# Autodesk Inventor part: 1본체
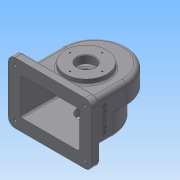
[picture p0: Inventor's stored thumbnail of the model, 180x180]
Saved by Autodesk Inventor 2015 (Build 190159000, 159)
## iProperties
Created: 2017-11
Part Number: 1본체
Material: 일반
Document SubType Name: Modeling
Designer: user
Density: 1 g/cm^3
Appearance: 기본값
Author: user
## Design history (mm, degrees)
sketch "스케치1"
  geometry: L1 (-58, -80)-(58, -80); L2 (-58, 0)-(-58, -80); L3 (58, 0)-(58, -80); A1 r 58 centre (0, 0) between (58, 0) and (-58, 0); 1 further point
  constraints: 6 end point, 2 point on circle, 2 tangent, 2 vertical, 1 centre point, 1 coincident, 1 horizontal
  dimensions: "d0" = 116 diameter of A1; "d1" = 80 distance from line of L1 point (0, 0)
extrude "돌출1" new body sketch "스케치1" stored distance "d2" = 38; taper "d3" = 0 deg
sketch "스케치2"
  geometry: L1 (-58, -80)-(58, -80) reference; L2 (58, -80)-(58, 0) reference; L3 (-58, 0)-(-58, -80) reference; L4 (-58, -80)-(58, -80); L5 (-58, -80)-(-58, -23); L6 (58, -80)-(58, -23); A1 r 58 centre (0, 0) between (58, 0) and (-58, 0) reference; A2 r 58 centre (0, -23) between (58, -23) and (-58, -23)
  constraints: 6 end point, 2 point on circle, 2 point on line, 1 centre point, 1 horizontal
  dimensions: "d6" = 57 distance from line of L1 A2.centre; "d7" = 58 radius of A2; "d8" = 23 distance of A1.centre A2.centre
extrude "돌출2" join sketch "스케치2" distance "d9" = 38; taper "d10" = 0 deg
sketch "스케치3"
  geometry: L1 (-58, -80)-(58, -80) reference; C1 r 37.5 at (0, -15); A1 r 58 centre (0, 0) between (58, 0) and (-58, 0) reference
  constraints: 1 centre point, 1 vertical alignment
  dimensions: "d11" = 75 diameter of C1; "d12" = 65 distance from line of L1 C1.centre
sketch "스케치4"
  geometry: L1 (-58, -80)-(58, -80) reference; C1 r 31 at (0, -15); 1 further point
  constraints: 1 centre point, 1 vertical alignment
  dimensions: "d13" = 62 diameter of C1; "d14" = 65 distance from line of L1 C1.centre
node "작업 평면1"
feature "쉘2" dims "d24" = 5
fillet "모깎기1" dims "d25" = 3
fillet "모깎기2" dims "d26" = 8
fillet "모깎기3" dims "d27" = 3
node "작업 평면2"
sketch "스케치6"
  geometry: L1 (-50, 19)-(50, 19) reference; C1 r 6 at (0, 0); 1 further point
  constraints: 1 centre point, 1 coincident
  dimensions: "d29" = 12 diameter of C1; "d30" = 19 distance from line of L1 C1.centre
extrude "돌출6" join sketch "스케치6" distance "d31" = 10; taper "d32" = 0 deg
extrude "돌출7" join sketch "스케치3" distance "d33" = 9; taper "d34" = 0 deg
extrude "돌출8" join sketch "스케치4" distance "d35" = 10; taper "d36" = 0 deg
sketch "스케치7"
  geometry: C1 r 37.5 at (0, 0) reference; C2 r 16 at (0, 0); 1 further point
  constraints: 1 centre point, 1 coincident
  dimensions: "d37" = 32 diameter of C2
extrude "돌출9" cut sketch "스케치7" distance "d38" = 21.75; taper "d39" = 0 deg
sketch "스케치8"
  geometry: C1 r 31 at (0, 0) reference; C2 r 16 at (0, 0); 1 further point
  constraints: 1 centre point, 1 coincident
  dimensions: "d40" = 32 diameter of C2
extrude "돌출10" cut sketch "스케치8" distance "d41" = 36.25; taper "d42" = 0 deg
sketch "스케치9"
  geometry: L1 (0, 0)-(100, 0) reference; L2 (-8, -8)-(-8, -68) reference; L3 (100, -76)-(0, -76) reference; L4 (108, -68)-(108, -8) reference; L5 (113, 17)-(-13, 17); L6 (-25, 5)-(-25, -81); L7 (-13, -93)-(113, -93); L8 (125, -81)-(125, 5); A1 r 8 centre (100, -8) between (108, -8) and (100, 0) reference; A2 r 8 centre (0, -8) between (0, 0) and (-8, -8) reference; A3 r 8 centre (0, -68) between (-8, -68) and (0, -76) reference; A4 r 8 centre (100, -68) between (100, -76) and (108, -68) reference; A5 r 12 centre (113, -81) between (113, -93) and (125, -81); A6 r 12 centre (113, 5) between (125, 5) and (113, 17); A7 r 12 centre (-13, 5) between (-13, 17) and (-25, 5); A8 r 12 centre (-13, -81) between (-25, -81) and (-13, -93); 5 further points
  constraints: 8 end point, 8 point on circle, 8 point on line, 8 tangent, 4 centre point, 3 equal radius, 2 parallel, 1 horizontal, 1 perpendicular
  dimensions: "d43" = 110 distance of point (125, -93) point (125, 17); "d44" = 150 distance of point (-25, -93) point (125, -93); "d45" = 17 distance between parallel lines of L7 L3; "d46" = 17 distance between parallel lines of L8 L4; "d86" = 12 radius of A5
extrude "돌출11" join sketch "스케치9" distance "d47" = 15; taper "d48" = 0 deg
sketch "스케치10"
  geometry: C1 r 16 at (0, 0) reference; 2 further points
  constraints: 1 vertical alignment
  dimensions: "d49" = 29 distance of point (0, 29) C1.centre
hole "구멍1" sketch "스케치10" at (0, 29) diameter "d50" = 2.459; stored, may be unused: countersink angle "d54" = 90 deg, drill point angle "d56" = 118 deg; dims "d51" = 6, "d52" = 4, "d53" = 2, "d55" = 8
sketch "스케치11"
  geometry: C1 r 16 at (0, 0) reference; 2 further points
  constraints: 1 vertical alignment
  dimensions: "d57" = 26 distance of point (0, 26) C1.centre
hole "구멍2" sketch "스케치11" at (0, 26) diameter "d58" = 2.459; stored, may be unused: countersink angle "d62" = 90 deg, drill point angle "d64" = 118 deg; dims "d59" = 6, "d60" = 4, "d61" = 2, "d63" = 8
fillet "모깎기4" dims "d71" = 3
sketch "스케치12"
  geometry: C1 r 6 at (0, 0) reference; 1 further point
  constraints: 1 coincident
hole "구멍3" sketch "스케치12" at (0, 0) diameter "d72" = 4.459; stored, may be unused: countersink angle "d76" = 90 deg, drill point angle "d78" = 118 deg; dims "d73" = 10, "d74" = 4, "d75" = 2, "d77" = 41.05
fillet "모깎기5" dims "d79" = 3
chamfer "모따기1" distance "d80" = 1; stored, may be unused: second distance "d81" = 2, angle "d82" = 45 deg
chamfer "모따기2" distance "d83" = 1; stored, may be unused: second distance "d84" = 2, angle "d85" = 45 deg
sketch "스케치13"
  geometry: A1 r 12 centre (113, 81) between (125, 81) and (113, 93) reference; A2 r 12 centre (-13, 81) between (-13, 93) and (-25, 81) reference; A3 r 12 centre (-13, -5) between (-25, -5) and (-13, -17) reference; A4 r 12 centre (113, -5) between (113, -17) and (125, -5) reference; 5 further points
  constraints: 4 coincident
hole "구멍4" sketch "스케치13" at (113, 81), (113, -5), (-13, -5), (-13, 81) diameter "d87" = 5; stored, may be unused: countersink angle "d91" = 90 deg, drill point angle "d93" = 0 deg; dims "d88" = 10, "d89" = 12, "d90" = 5, "d92" = 41.05
fillet "모깎기6" dims "d94" = 3
fillet "모깎기7" dims "d95" = 3
node "작업 평면3"
sketch "스케치14"
  geometry: L1 (-80, -62)-(-80, 24) reference; L2 (0, 19)-(-62, 19) reference; 2 further points
  constraints: 1 other
  dimensions: "d97" = 40 distance from line of L1 point (-40, -19); "d98" = 38 distance from line of L2 point (-40, -19)
feature "엠보싱1" sketch "스케치14" dims "d99" = 0.5, "d100" = 0
node "솔리드1"
pattern_circular "원형 패턴1" dims angle "d66" = 360 deg
pattern_circular "원형 패턴2" dims angle "d69" = 360 deg
other parameters: "d5" = 116, "d15" = 64, "d28" = 64
